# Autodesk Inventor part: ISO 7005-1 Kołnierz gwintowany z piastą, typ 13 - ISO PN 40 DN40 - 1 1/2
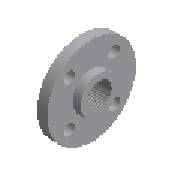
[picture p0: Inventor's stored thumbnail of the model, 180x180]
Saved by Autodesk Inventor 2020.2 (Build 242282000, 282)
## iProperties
Manager: www.cadconsulting.pl
Company: Fabian Stasiak CAD Consulting
IsCustomPart: 0
Created: 2014-02
Part Number: ISO 7005-1 Kołnierz gwintowany z piastą, typ 13 - ISO PN 40 DN40 - 1 1/2
Material: Stal
Description: Kołnierze metalowe - Część 1: Kołnierze stalowe - Kołnierz gwintowany z piastą, typ 13 - ISO PN 40
Document SubType Name: Modeling
Standard: ISO 7005-1
Designer: F.Stasiak
Standard Revision: First edition 1992-04-15
Standards Organization: ISO
Language: pl-PL
Size Designation: DN40 - 1 1/2
Categories: <MemberInstance><Categories><Category DisplayName="Rury cienko- i grubościenne" InternalName="4347fa0f-2144-441d-94cd-e3e15c92b736" Mnemonic="TUBEANDPIPE"><Cate
Density: 1 g/cm^3
Appearance: Płyta
Catalog Web Link: www.expertbooks.pl
NAME: PIPING: ISO 7005-1 Hubbed Threaded Flange Type 13 - PN 40
DATA: <meta><inlinegroups number="1" deflen="3"></inlinegroups><connections number="2"></connections><angles><a>3.14159265358979</a></angles></meta>
Author: F.Stasiak
Subject: Zbiór ćwiczeń. Autodesk Inventor 2020. Kurs Professional
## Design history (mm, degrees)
sketch "Sketch1"
  geometry: L1 (0, 0)-(32, 0) reference; L2 (0, 21.422)-(0, 42); L3 (0, 42)-(2, 42); L4 (2, 75)-(18, 75); L5 (0, 21.422)-(0, 0); L6 (2, 75)-(2, 42); L7 (18, 75)-(18, 35); L8 (18, 35)-(32, 35); L9 (32, 35)-(32, 22.422); L10 (32, 22.422)-(0, 21.422); L11 (32, 22.422)-(32, 0)
  constraints: 22 end point, 3 parallel, 3 perpendicular, 1 collinear, 1 horizontal
  dimensions: "d0" = 84 diameter of L3 L1 (= D1); "d1" = 150 diameter of L4 L1 (= D); "d2" = 18 distance between parallel lines of L2 L7 (= C2); "d3" = 70 diameter of L7.end L1 (= N2); "d4" = 2 distance between parallel lines of L2 L6 (= F1); "d9" = 1.78991 deg angle of L1 L10; "d10" = 44.845 diameter of L9.end L1 (= MD); "d12" = 32 distance between parallel lines of L9 L2 (= H1)
revolve "Revolution1" stored, may be unused: angle "d11" = 90 deg
sketch "Sketch2"
  geometry: L1 (0, 0)-(0, 55); L2 (0, 0)-(38.891, 38.891); C1 r 42 at (0, 0) reference; C2 r 75 at (0, 0) reference; C3 r 9 at (38.891, 38.891); A1 r 55 centre (0, 0) between (0, 55) and (38.891, 38.891)
  constraints: 4 end point, 2 centre point, 2 coincident, 2 point on circle, 1 vertical
  dimensions: "d13" = 18 diameter of C3 (= L); "d14" = 110 diameter of A1 (= K1); "d15" = 45 deg angle of L1 L2 (computed from NU)
extrude "Extrusion1" cut sketch "Sketch2" distance "d5" = 18 (= C2); taper "d6" = 0 deg
pattern_circular "Circular Pattern1" dims angle "d8" = 360 deg
workaxis "Work Axis3"
workpoint "Work Point4"
workaxis "Work Axis4"
workpoint "Work Point5"
workaxis "Work Axis5"
workaxis "Work Axis6"
workpoint "Work Point6"
body "Solid1"
feature "Gwint1" dims "d122" = 10, "d123" = 0
other parameters: "C2" = 18 [user parameter; used in 2 equation terms], "D" = 150 [user parameter; used in 1 equation term], "K1" = 110 [user parameter; used in 1 equation term], "L" = 18 [user parameter; used in 1 equation term], "N2" = 70 [user parameter; used in 1 equation term], "D1" = 84 [user parameter; used in 1 equation term], "H1" = 32 [user parameter; used in 1 equation term], "F1" = 2 [user parameter; used in 1 equation term], "MD" = 44.845 [user parameter; used in 1 equation term], "Size_Designation" = 12.345 [user parameter]
